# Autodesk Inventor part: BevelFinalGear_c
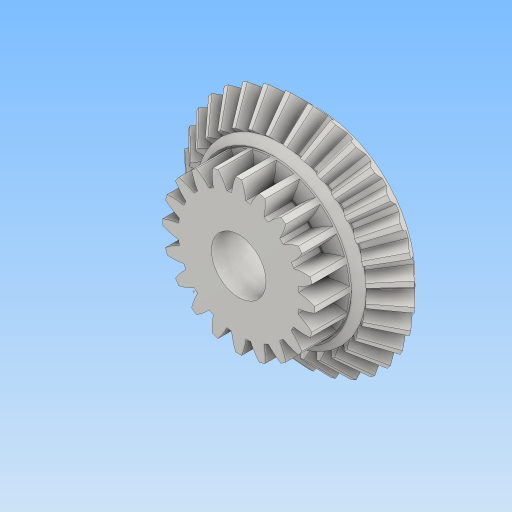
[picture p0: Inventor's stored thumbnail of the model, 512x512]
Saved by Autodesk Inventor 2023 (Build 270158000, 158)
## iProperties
Created: 2024-01
Part Number: BevelFinalGear_c
Material: 一般
Document SubType Name: Modeling
Designer: kumagai
Density: 1 g/cm^3
Appearance: 既定
Author: kumagai
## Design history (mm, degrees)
derived "BevelFinalGear.iam"
node "ソリッド1"
node "かさ歯車1:1" dims "d0" = 10
node "上側の点"
node "平歯車2:1" dims "d0" = 10
